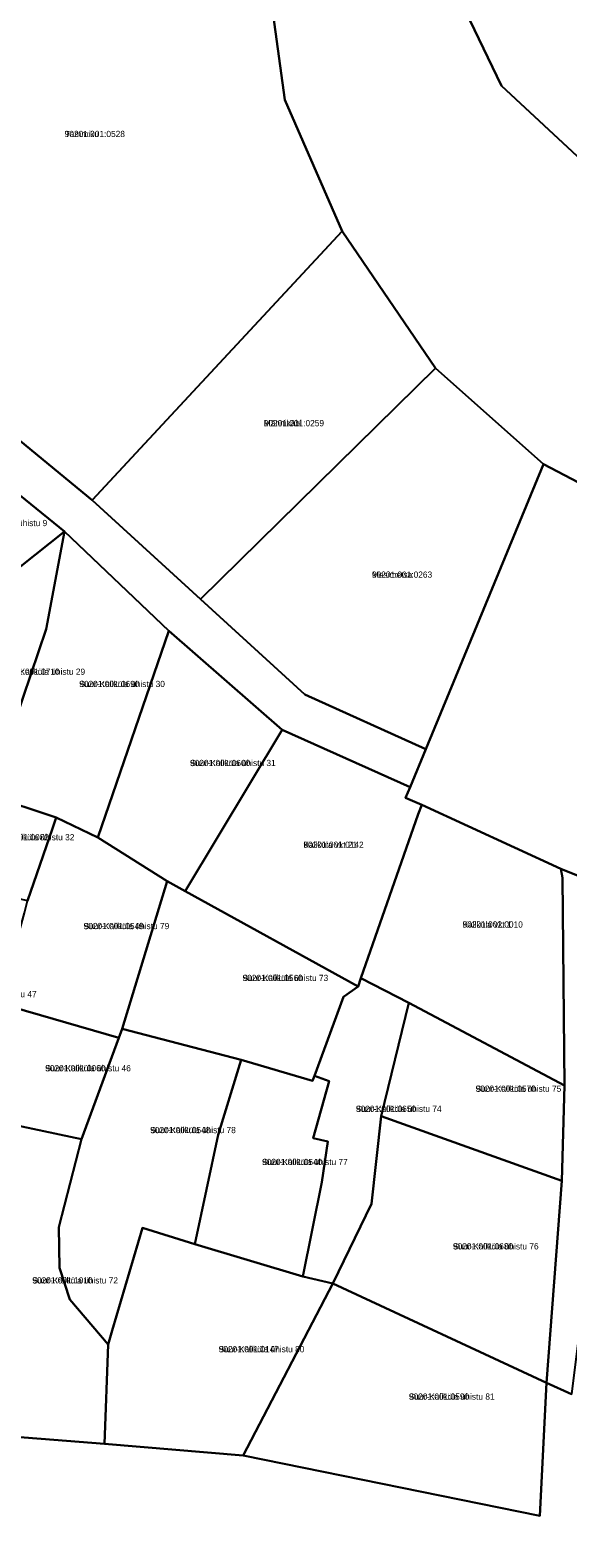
# Model space of a CAD drawing. Extents: x 634518 to 667988, y 6584667 to 6604739.
# Drawn here: x 639280.5 to 639410, y 6598757.6 to 6599120.4 of the extents above; entities that cross this region are included whole.
import ezdxf

# ---------------------------------------------------------------- set-up
doc = ezdxf.new("R2010")
doc.units = 0
for name, color, linetype in [('L_AADRESS', 7, 'Continuous'), ('PIIR', 7, 'Continuous'), ('TUNNUS', 7, 'Continuous')]:
    doc.layers.add(name, color=color, linetype=linetype)

msp = doc.modelspace()

# ---------------------------------------------------------------- linework, layer by layer
at = {"layer": 'PIIR'}
for points in [[(639100.56, 6599329.51), (639118.72, 6599284.25), (639145.3, 6599252.04), (639206.86, 6599262.51), (639252.25, 6599289.18), (639304.28, 6599296.85), (639350.81, 6599291.05), (639379.7, 6599278.52), (639387.08, 6599252.18), (639381.42, 6599229.17), (639376.55, 6599190.19), (639377.67, 6599140.79), (639393.99, 6599106.97), (639433.76, 6599069.98)], [(639433.76, 6599069.98), (639393.99, 6599106.97), (639377.67, 6599140.79), (639376.55, 6599190.19), (639381.42, 6599229.17), (639387.08, 6599252.18), (639379.7, 6599278.52), (639350.81, 6599291.05), (639304.28, 6599296.85), (639252.25, 6599289.18), (639206.86, 6599262.51), (639145.3, 6599252.04), (639118.72, 6599284.25), (639100.56, 6599329.51)], [(639441.3, 6598996.4), (639404.07, 6599015.97), (639378.12, 6599039.05), (639355.62, 6599071.96), (639341.87, 6599103.62), (639333.44, 6599165.02), (639297.96, 6599174.25), (639246.74, 6599187.59), (639245.19, 6599188.04), (639243.23, 6599188.58), (639209.09, 6599197.48), (639173.59, 6599187.14), (639153.27, 6599188.56), (639136.08, 6599200.34), (639113.01, 6599217.01), (639066.11, 6599272.45), (639036.47, 6599305.14), (638997.65, 6599321.26)], [(639020.26, 6598657.37), (639047.45, 6598801.49), (639067.79, 6598798.19), (639077.92, 6598797.15), (639086.39, 6598796.37), (639096.85, 6598795.57), (639110.57, 6598794.77), (639124.2, 6598793.78), (639134.46, 6598792.96), (639145.94, 6598792.18), (639157.13, 6598791.46), (639167.66, 6598790.48), (639186.79, 6598790.92), (639198.99, 6598791.25), (639224.57, 6598790.15), (639237.51, 6598788.05), (639246.31, 6598786.53), (639266.83, 6598782.66), (639298.45, 6598780.16), (639331.83, 6598777.4), (639403.21, 6598762.87), (639404.8, 6598794.89), (639410.81, 6598792.11)]]:
    msp.add_lwpolyline(points, dxfattribs=at)
for points in [[(639295.43, 6599007.23), (639223.67, 6599066.34), (639222.06, 6599067.35), (639238.97, 6599090.63), (639242.74, 6599096.83), (639243.91, 6599100), (639245.63, 6599106.61), (639247.04, 6599113.24), (639246.5, 6599122.2), (639248.51, 6599133.96), (639249.45, 6599160.16), (639244.87, 6599174.9), (639243.83, 6599180.32), (639245.19, 6599188.04), (639246.74, 6599187.59), (639297.96, 6599174.25), (639333.44, 6599165.02), (639341.87, 6599103.62), (639355.62, 6599071.96)], [(639166.41, 6599091.4), (639138.6, 6599108), (639114.82, 6599117.34), (639118.65, 6599126.67), (639143.03, 6599116.99), (639220.59, 6599068.27), (639222.06, 6599067.35), (639223.67, 6599066.34), (639295.43, 6599007.23), (639321.52, 6598983.41), (639346.67, 6598960.5), (639375.78, 6598947.36), (639371.97, 6598938.2), (639341.23, 6598951.98), (639313.88, 6598975.86), (639288.82, 6598999.72), (639259.24, 6599023.6), (639238.53, 6599036.45), (639217.78, 6599059.27), (639187.67, 6599076.21)], [(639295.43, 6599007.23), (639355.62, 6599071.96), (639378.12, 6599039.05), (639321.52, 6598983.41)], [(639321.52, 6598983.41), (639378.12, 6599039.05), (639404.07, 6599015.97), (639375.78, 6598947.36), (639346.67, 6598960.5)], [(639241.46, 6598986.1), (639243.2, 6598989.99), (639259.24, 6599023.6), (639288.8, 6598999.71), (639267.55, 6598982.88), (639256.15, 6598984.38)], [(639404.07, 6599015.97), (639441.3, 6598996.4), (639457.13, 6598995.11), (639429.15, 6598915.68), (639427.48, 6598910.88), (639408.31, 6598918.58), (639374.8, 6598933.94), (639370.91, 6598935.65), (639371.97, 6598938.2), (639375.78, 6598947.36)], [(639270.78, 6598936.2), (639259.44, 6598939.94), (639257.47, 6598940.45), (639258.17, 6598942.36), (639270.69, 6598980.86), (639267.55, 6598982.88), (639288.8, 6598999.71), (639284.4, 6598976.23), (639271.38, 6598938.02)], [(639270.78, 6598936.2), (639271.38, 6598938.02), (639284.4, 6598976.23), (639288.8, 6598999.71), (639313.89, 6598975.84), (639296.8, 6598926.09), (639286.75, 6598930.92)], [(639313.51, 6598915.58), (639296.8, 6598926.09), (639313.89, 6598975.84), (639341.23, 6598951.98), (639317.82, 6598913.21), (639315.66, 6598914.36)], [(639341.23, 6598951.98), (639371.97, 6598938.2), (639370.91, 6598935.65), (639374.8, 6598933.94), (639373.95, 6598931.71), (639360.15, 6598892.25), (639359.45, 6598890.28), (639317.82, 6598913.21)], [(639259.01, 6598938.25), (639259.44, 6598939.94), (639270.78, 6598936.2), (639286.75, 6598930.92), (639285.94, 6598928.24), (639279.92, 6598910.88), (639254.25, 6598916.93), (639254.49, 6598918.07)], [(639374.8, 6598933.94), (639408.31, 6598918.58), (639408.71, 6598916.37), (639409.12, 6598866.41), (639371.68, 6598886.3), (639360.15, 6598892.25), (639373.95, 6598931.71)], [(639285.94, 6598928.24), (639286.75, 6598930.92), (639296.8, 6598926.09), (639313.51, 6598915.58), (639302.64, 6598880.07), (639301.91, 6598877.89), (639273.27, 6598886.15), (639273.71, 6598887.89), (639279.15, 6598907.98), (639279.92, 6598910.88)], [(639408.71, 6598916.37), (639408.31, 6598918.58), (639427.48, 6598910.88), (639429.32, 6598910.2), (639428.72, 6598908.05), (639425.68, 6598898.39), (639419.13, 6598901.43), (639416.94, 6598894.89), (639423.86, 6598891.91), (639415.88, 6598862.84), (639414.81, 6598850.92), (639415.66, 6598832.88), (639415.17, 6598828.71), (639414.29, 6598819.82), (639410.81, 6598792.11), (639404.8, 6598794.89), (639408.49, 6598843.5), (639409.12, 6598866.41)], [(639302.64, 6598880.07), (639313.51, 6598915.58), (639315.66, 6598914.36), (639317.82, 6598913.21), (639359.45, 6598890.28), (639355.99, 6598887.73), (639348.96, 6598868.71), (639348.51, 6598867.52), (639331.36, 6598872.57)], [(639360.15, 6598892.25), (639371.68, 6598886.3), (639364.99, 6598859.05), (639362.69, 6598837.92), (639353.36, 6598818.75), (639346.2, 6598820.48), (639350.72, 6598843.18), (639352.22, 6598852.92), (639348.66, 6598853.74), (639352.51, 6598867.48), (639348.96, 6598868.71), (639355.99, 6598887.73), (639359.45, 6598890.28)], [(639267.12, 6598860.53), (639273.27, 6598886.15), (639301.91, 6598877.89), (639292.87, 6598853.52), (639266.77, 6598859.03)], [(639371.68, 6598886.3), (639409.12, 6598866.41), (639408.49, 6598843.5), (639364.99, 6598859.05)], [(639301.91, 6598877.89), (639302.64, 6598880.07), (639331.36, 6598872.57), (639331.04, 6598871.54), (639325.82, 6598854.55), (639320.19, 6598828.27), (639307.54, 6598832.17), (639300.29, 6598807.46), (639299.29, 6598804.06), (639290.12, 6598814.94), (639287.63, 6598822.58), (639287.46, 6598832.3), (639292.87, 6598853.52)], [(639320.19, 6598828.27), (639325.82, 6598854.55), (639331.04, 6598871.54), (639331.36, 6598872.57), (639348.51, 6598867.52), (639348.96, 6598868.71), (639352.51, 6598867.48), (639348.66, 6598853.74), (639352.22, 6598852.92), (639350.72, 6598843.18), (639346.2, 6598820.48)], [(639269.39, 6598822.96), (639262.79, 6598828.52), (639265.72, 6598857.2), (639265.93, 6598859.21), (639266.77, 6598859.03), (639292.87, 6598853.52), (639287.46, 6598832.3), (639287.63, 6598822.58), (639290.12, 6598814.94), (639299.29, 6598804.06), (639298.45, 6598780.16), (639266.83, 6598782.66)], [(639362.69, 6598837.92), (639364.99, 6598859.05), (639408.49, 6598843.5), (639404.8, 6598794.89), (639353.36, 6598818.75)], [(639307.54, 6598832.17), (639320.19, 6598828.27), (639346.2, 6598820.48), (639353.36, 6598818.75), (639331.83, 6598777.4), (639298.45, 6598780.16), (639299.29, 6598804.06), (639300.29, 6598807.46)], [(639353.36, 6598818.75), (639404.8, 6598794.89), (639403.21, 6598762.87), (639331.83, 6598777.4)]]:
    msp.add_lwpolyline(points, close=True, dxfattribs=at)

# ---------------------------------------------------------------- texts
at = {"layer": 'L_AADRESS'}
for s, p in [('Tammiku', (639288.84, 6599094.64)), ('Männikäbi', (639336.77, 6599025.05)), ('Suur-Kaliküla ühistu 9', (639265.13, 6599001.02)), ('Mesimetsa', (639362.8, 6598988.6)), ('Suur-Kaliküla ühistu 29', (639273.13, 6598965.24)), ('Suur-Kaliküla ühistu 30', (639292.34, 6598962.29)), ('Suur-Kaliküla ühistu 31', (639319.01, 6598943.28)), ('Suur-Kaliküla ühistu 32', (639270.55, 6598925.41)), ('Kaliküla vkt 21', (639346.31, 6598923.61)), ('Kaliküla vkt 1', (639384.63, 6598904.42)), ('Suur-Kaliküla ühistu 79', (639293.39, 6598904.04)), ('Suur-Kaliküla ühistu 73', (639331.65, 6598891.55)), ('Suur-Kaliküla ühistu 47', (639261.46, 6598887.65)), ('Suur-Kaliküla ühistu 46', (639284.14, 6598869.83)), ('Suur-Kaliküla ühistu 75', (639387.75, 6598864.9)), ('Suur-Kaliküla ühistu 74', (639358.94, 6598860.06)), ('Suur-Kaliküla ühistu 78', (639309.41, 6598854.95)), ('Suur-Kaliküla ühistu 77', (639336.35, 6598847.27)), ('Suur-Kaliküla ühistu 76', (639382.3, 6598826.97)), ('Suur-Kaliküla ühistu 72', (639281.04, 6598818.78)), ('Suur-Kaliküla ühistu 80', (639325.91, 6598802.22)), ('Suur-Kaliküla ühistu 81', (639371.7, 6598790.81))]:
    msp.add_text(s, height=1.5, dxfattribs=at).set_placement(p)
at = {"layer": 'TUNNUS'}
for s, p in [('90201:001:0528', (639288.84, 6599094.64)), ('90201:001:0259', (639336.77, 6599025.05)), ('90201:001:0263', (639362.8, 6598988.6)), ('90201:001:0710', (639273.13, 6598965.24)), ('90201:001:0690', (639292.34, 6598962.29)), ('90201:001:0600', (639319.01, 6598943.28)), ('90201:001:0082', (639270.55, 6598925.41)), ('90201:001:0142', (639346.31, 6598923.61)), ('90201:002:0010', (639384.63, 6598904.42)), ('90201:001:0549', (639293.39, 6598904.04)), ('90201:001:0560', (639331.65, 6598891.55)), ('90201:001:0060', (639284.14, 6598869.83)), ('90201:001:0570', (639387.75, 6598864.9)), ('90201:001:0650', (639358.94, 6598860.06)), ('90201:001:0548', (639309.41, 6598854.95)), ('90201:001:0540', (639336.35, 6598847.27)), ('90201:001:0680', (639382.3, 6598826.97)), ('90201:001:1010', (639281.04, 6598818.78)), ('90201:001:0147', (639325.91, 6598802.22)), ('90201:001:0590', (639371.7, 6598790.81))]:
    msp.add_text(s, height=1.5, dxfattribs=at).set_placement(p)

doc.saveas('drawing.dxf')
